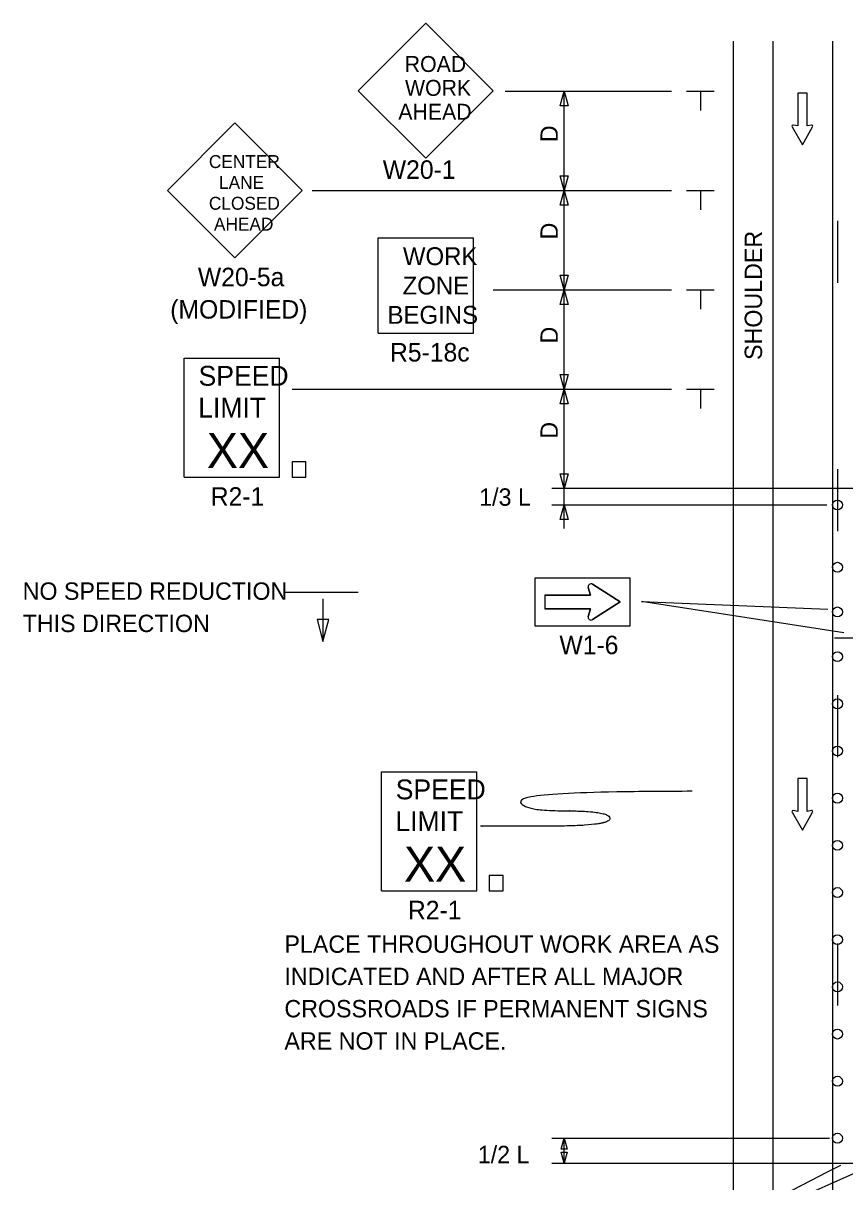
# Model space of a CAD drawing. Extents: x 16750 to 18306, y 5932 to 6925.
# Drawn here: x 16749.5 to 17080.6, y 6458.2 to 6924.9 of the extents above; entities that cross this region are included whole.
import ezdxf

# ---------------------------------------------------------------- set-up
doc = ezdxf.new("R2010")
doc.units = 0
for name, color, linetype in [('BORDER', 7, 'Continuous'), ('Level 3', 7, 'Continuous'), ('MT_SCRATCH_LEVEL_A', 7, 'Continuous'), ('MT_SCRATCH_LEVEL_E', 7, 'Continuous'), ('PAVT_EDGE_EX', 7, 'Continuous'), ('TRAFFIC_SIGNS_PR', 7, 'Continuous'), ('TYPICAL_EX', 7, 'Continuous'), ('TYPICAL_TEXT_DIMEN_EX', 7, 'Continuous'), ('TYPICAL_TEXT_DIMEN_PR', 7, 'Continuous')]:
    doc.layers.add(name, color=color, linetype=linetype)

msp = doc.modelspace()

# ---------------------------------------------------------------- linework, layer by layer
at = {"layer": 'BORDER'}
msp.add_line((17051.59, 6917.57), (17051.59, 6063.18), dxfattribs=at)
at = {"layer": 'Level 3'}
msp.add_line((17080.12, 6679.35), (16998.62, 6691.92), dxfattribs=at)
at = {"layer": 'MT_SCRATCH_LEVEL_A'}
for p, q in [((16911.72, 6924.87), (16884.53, 6897.68)), ((16938.9, 6897.68), (16911.72, 6924.87)), ((17075.59, 6917.57), (17075.59, 6063.18)), ((16884.53, 6897.68), (16911.72, 6870.49)), ((16911.72, 6870.49), (16938.9, 6897.68))]:
    msp.add_line(p, q, dxfattribs=at)
for points in [[(17077.59, 6845.22), (17077.59, 6820.22)], [(17077.59, 6745.22), (17077.59, 6720.22)], [(17077.59, 6654.22), (17077.59, 6629.22)], [(17077.59, 6554.22), (17077.59, 6529.22)]]:
    msp.add_lwpolyline(points, dxfattribs=at)
at = {"layer": 'MT_SCRATCH_LEVEL_E'}
for p, q in [((17065.33, 6896.74), (17061.59, 6896.74)), ((17061.59, 6896.74), (17061.59, 6883.48)), ((17065.33, 6896.74), (17061.59, 6896.74)), ((17061.59, 6896.74), (17061.59, 6883.48)), ((17065.33, 6883.48), (17065.33, 6896.74)), ((17065.33, 6883.48), (17065.33, 6896.74)), ((17061.59, 6883.48), (17059.81, 6883.79)), ((17061.59, 6883.48), (17059.81, 6883.79)), ((17067.11, 6883.79), (17065.33, 6883.48)), ((17067.11, 6883.79), (17065.33, 6883.48)), ((17059.33, 6883.11), (17063.48, 6875.87)), ((17059.33, 6883.11), (17063.48, 6875.87)), ((17063.48, 6875.87), (17067.59, 6883.11)), ((17063.48, 6875.87), (17067.59, 6883.11)), ((17065.33, 6620.66), (17061.59, 6620.66)), ((17061.59, 6620.66), (17061.59, 6607.4)), ((17065.33, 6620.66), (17061.59, 6620.66)), ((17061.59, 6620.66), (17061.59, 6607.4)), ((17065.33, 6607.4), (17065.33, 6620.66)), ((17065.33, 6607.4), (17065.33, 6620.66)), ((17059.33, 6607.03), (17063.48, 6599.79)), ((17059.33, 6607.03), (17063.48, 6599.79)), ((17061.59, 6607.4), (17059.81, 6607.72)), ((17061.59, 6607.4), (17059.81, 6607.72)), ((17063.48, 6599.79), (17067.59, 6607.03)), ((17063.48, 6599.79), (17067.59, 6607.03)), ((17067.11, 6607.72), (17065.33, 6607.4)), ((17067.11, 6607.72), (17065.33, 6607.4))]:
    msp.add_line(p, q, dxfattribs=at)
for centre, start, end in [((17059.74, 6883.33), 80.0362, 209.7731), ((17059.74, 6883.33), 80.0362, 209.7731), ((17067.18, 6883.33), 330.4248, 99.9638), ((17067.18, 6883.33), 330.4248, 99.9638), ((17059.74, 6607.26), 80.0362, 209.7731), ((17059.74, 6607.26), 80.0362, 209.7731), ((17067.18, 6607.26), 330.4248, 99.9638), ((17067.18, 6607.26), 330.4248, 99.9638)]:
    msp.add_arc(centre, 0.463, start, end, dxfattribs=at)
at = {"layer": 'PAVT_EDGE_EX'}
msp.add_line((17035.59, 6917.57), (17035.59, 6063.18), dxfattribs=at)
at = {"layer": 'TRAFFIC_SIGNS_PR'}
for p, q in [((16884.53, 6897.68), (16911.72, 6924.87)), ((16911.72, 6924.87), (16938.9, 6897.68)), ((16911.72, 6870.49), (16884.53, 6897.68)), ((16938.9, 6897.68), (16911.72, 6870.49)), ((16834.77, 6884.67), (16807.62, 6857.51)), ((16861.92, 6857.51), (16834.77, 6884.67)), ((16807.62, 6857.51), (16834.77, 6830.36)), ((16834.77, 6830.36), (16861.92, 6857.51)), ((16892.51, 6800.03), (16892.51, 6838.43)), ((16892.51, 6838.43), (16930.91, 6838.43)), ((16930.91, 6800.03), (16930.91, 6838.43)), ((16892.51, 6800.03), (16930.91, 6800.03)), ((16814.42, 6789.98), (16852.82, 6789.98)), ((16814.42, 6741.98), (16814.42, 6789.98)), ((16852.82, 6741.98), (16852.82, 6789.98)), ((16814.42, 6741.98), (16852.82, 6741.98)), ((16978.04, 6694.55), (16977.2, 6697.61)), ((16978.88, 6698.86), (16990.04, 6691.75)), ((16959.64, 6694.55), (16978.04, 6694.55)), ((16959.64, 6694.55), (16959.64, 6688.95)), ((16978.04, 6688.95), (16959.64, 6688.95)), ((16977.2, 6685.89), (16978.04, 6688.95)), ((16990.04, 6691.75), (16978.88, 6684.65)), ((16893.86, 6623.39), (16932.26, 6623.39)), ((16893.86, 6575.39), (16893.86, 6623.39)), ((16932.26, 6575.39), (16932.26, 6623.39)), ((16893.86, 6575.39), (16932.26, 6575.39))]:
    msp.add_line(p, q, dxfattribs=at)
for points in [[(16857.84, 6741.98), (16863.43, 6741.98), (16863.43, 6748.15), (16857.84, 6748.15)], [(16955.64, 6682.15), (16994.04, 6682.15), (16994.04, 6701.35), (16955.64, 6701.35)], [(16937.27, 6575.39), (16942.87, 6575.39), (16942.87, 6581.56), (16937.27, 6581.56)]]:
    msp.add_lwpolyline(points, close=True, dxfattribs=at)
for points in [[(16977.2, 6697.61), (16978.04, 6694.55), (16959.64, 6694.55), (16959.64, 6688.95), (16978.04, 6688.95), (16977.2, 6685.89)], [(16978.88, 6684.65), (16990.04, 6691.75), (16978.88, 6698.86)]]:
    msp.add_lwpolyline(points, dxfattribs=at)
for centre in [(17077.59, 6730.81), (17077.59, 6705.72), (17077.59, 6687.72), (17077.59, 6669.72), (17077.59, 6650.72), (17077.59, 6631.72), (17077.59, 6612.72), (17077.59, 6593.72), (17077.59, 6574.72), (17077.59, 6555.72), (17077.59, 6536.72), (17077.59, 6517.72), (17077.59, 6498.72), (17077.59, 6475.75)]:
    msp.add_circle(centre, 2, dxfattribs=at)
for centre, start, end in [((16978.28, 6697.91), 57.5304, 195.3269), ((16978.28, 6697.91), 57.5304, 195.3269), ((16978.28, 6685.6), 164.6731, 302.4696), ((16978.28, 6685.6), 164.6731, 302.4696)]:
    msp.add_arc(centre, 1.12, start, end, dxfattribs=at)
at = {"layer": 'TYPICAL_EX'}
for p, q in [((17016.74, 6897.47), (17027.99, 6897.47)), ((17022.37, 6897.47), (17022.37, 6889.69)), ((17016.74, 6857.47), (17027.99, 6857.47)), ((17022.37, 6857.47), (17022.37, 6849.69)), ((17016.74, 6817.47), (17027.99, 6817.47)), ((17022.37, 6817.47), (17022.37, 6809.69)), ((17016.74, 6777.47), (17027.99, 6777.47)), ((17022.37, 6777.47), (17022.37, 6769.69)), ((17087.66, 6677.17), (17076.41, 6677.17))]:
    msp.add_line(p, q, dxfattribs=at)
at = {"layer": 'TYPICAL_TEXT_DIMEN_PR'}
for p, q in [((16943.76, 6897.47), (17010.69, 6897.47)), ((16965.92, 6891.61), (16967.49, 6897.47)), ((16967.49, 6897.47), (16969.06, 6891.61)), ((16967.49, 6857.47), (16967.49, 6897.47)), ((16967.49, 6891.61), (16965.92, 6891.61)), ((16969.06, 6891.61), (16967.49, 6891.61)), ((16967.49, 6857.47), (16965.92, 6863.34)), ((16965.92, 6863.34), (16967.49, 6863.34)), ((16967.49, 6863.34), (16969.06, 6863.34)), ((16969.06, 6863.34), (16967.49, 6857.47)), ((16866.01, 6857.47), (17010.69, 6857.47)), ((16965.92, 6851.61), (16967.49, 6857.47)), ((16967.49, 6817.47), (16967.49, 6857.47)), ((16967.49, 6857.47), (16969.06, 6851.61)), ((16967.49, 6851.61), (16965.92, 6851.61)), ((16969.06, 6851.61), (16967.49, 6851.61)), ((16967.49, 6817.47), (16965.92, 6823.34)), ((16965.92, 6823.34), (16967.49, 6823.34)), ((16967.49, 6823.34), (16969.06, 6823.34)), ((16969.06, 6823.34), (16967.49, 6817.47)), ((16938.9, 6817.47), (17010.69, 6817.47)), ((16965.92, 6811.61), (16967.49, 6817.47)), ((16967.49, 6817.47), (16969.06, 6811.61)), ((16967.49, 6777.47), (16967.49, 6817.47)), ((16967.49, 6811.61), (16965.92, 6811.61)), ((16969.06, 6811.61), (16967.49, 6811.61)), ((16967.49, 6777.47), (16965.92, 6783.34)), ((16965.92, 6783.34), (16967.49, 6783.34)), ((16967.49, 6783.34), (16969.06, 6783.34)), ((16969.06, 6783.34), (16967.49, 6777.47)), ((16857.91, 6777.47), (17010.69, 6777.47)), ((16965.92, 6771.61), (16967.49, 6777.47)), ((16967.49, 6777.47), (16969.06, 6771.61)), ((16967.49, 6737.47), (16967.49, 6777.47)), ((16967.49, 6771.61), (16965.92, 6771.61)), ((16969.06, 6771.61), (16967.49, 6771.61)), ((16967.49, 6737.47), (16965.92, 6743.34)), ((16965.92, 6743.34), (16967.49, 6743.34)), ((16967.49, 6743.34), (16969.06, 6743.34)), ((16969.06, 6743.34), (16967.49, 6737.47)), ((17093.86, 6737.47), (16962.49, 6737.47)), ((16967.49, 6721.4), (16967.49, 6737.47)), ((16962.49, 6730.81), (17073.36, 6730.81)), ((16965.92, 6724.94), (16967.49, 6730.81)), ((16967.49, 6730.81), (16969.06, 6724.94)), ((16967.49, 6724.94), (16965.92, 6724.94)), ((16969.06, 6724.94), (16967.49, 6724.94)), ((16884.47, 6695.5), (16855.03, 6695.5)), ((16870.29, 6693), (16870.29, 6675.88)), ((16998.62, 6691.92), (17073.76, 6688.79)), ((16870.29, 6684.67), (16867.94, 6684.67)), ((16867.94, 6684.67), (16870.29, 6675.88)), ((16870.29, 6675.88), (16872.65, 6684.67)), ((16872.65, 6684.67), (16870.29, 6684.67)), ((16962.49, 6475.75), (17074.39, 6475.75)), ((16966.31, 6471.35), (16967.49, 6475.75)), ((16967.49, 6475.75), (16968.67, 6471.35)), ((16967.49, 6465.75), (16967.49, 6475.75)), ((16967.49, 6471.35), (16966.31, 6471.35)), ((16967.49, 6465.75), (16966.31, 6470.15)), ((16966.31, 6470.15), (16967.49, 6470.15)), ((16968.67, 6471.35), (16967.49, 6471.35)), ((16967.49, 6470.15), (16968.67, 6470.15)), ((16968.67, 6470.15), (16967.49, 6465.75)), ((16962.49, 6465.75), (17094.29, 6465.75)), ((17001.57, 6424.99), (17091.23, 6464.75)), ((17073.53, 6462.17), (17078.94, 6464.96)), ((17001.57, 6424.99), (17073.53, 6462.17))]:
    msp.add_line(p, q, dxfattribs=at)
msp.add_open_spline([(17019.08, 6615.49), (16950, 6615.49), (16950, 6607.61), (16985.96, 6607.61), (16985.96, 6601.45), (16937.66, 6601.45), (16933.72, 6601.45)], degree=2, dxfattribs=at)

# ---------------------------------------------------------------- texts
at = {"layer": 'TRAFFIC_SIGNS_PR'}
for s, height, p in [('ROAD', 6.408, (16903.25, 6905.22)), ('WORK', 6.408, (16903.36, 6895.61)), ('AHEAD', 6.408, (16900.66, 6886)), ('CENTER', 5.2, (16824.35, 6866.52)), ('W20-1', 7.449, (16894.4, 6862.17)), ('LANE', 5.2, (16828.42, 6858.12)), ('CLOSED', 5.2, (16824.35, 6849.72)), ('AHEAD', 5.2, (16826.38, 6841.32)), ('WORK', 7.217, (16902.51, 6827.4)), ('W20-5a', 7.44, (16819.91, 6818.92)), ('ZONE', 7.217, (16902.39, 6815.59)), ('(MODIFIED)', 7.44, (16808.77, 6805.88)), ('BEGINS', 7.217, (16896.32, 6803.78)), ('R5-18c', 7.44, (16897.32, 6788.59)), ('SPEED', 8, (16820.19, 6778.84)), ('LIMIT', 8, (16820.03, 6766.04)), ('XX', 14.031, (16823.54, 6745.73)), ('R2-1', 7.44, (16825.1, 6730.53)), ('W1-6', 7.44, (16965.58, 6670.71)), ('SPEED', 8, (16899.62, 6612.25)), ('LIMIT', 8, (16899.46, 6599.45)), ('XX', 14.031, (16902.97, 6579.15)), ('R2-1', 7.44, (16904.53, 6563.95)), ('PLACE THROUGHOUT WORK AREA AS', 7, (16854.78, 6550.43)), ('INDICATED AND AFTER ALL MAJOR', 7, (16854.78, 6537.43)), ('CROSSROADS IF PERMANENT SIGNS', 7, (16854.78, 6524.43)), ('ARE NOT IN PLACE.', 7, (16854.78, 6511.43))]:
    msp.add_text(s, height=height, dxfattribs=at).set_placement(p)
at = {"layer": 'TYPICAL_TEXT_DIMEN_EX'}
msp.add_text('SHOULDER', height=7, rotation=90, dxfattribs=at).set_placement((17047.22, 6789.22))
at = {"layer": 'TYPICAL_TEXT_DIMEN_PR'}
for p in [(16964.93, 6876.93), (16964.93, 6837.75), (16964.93, 6795.84), (16964.93, 6757.5)]:
    msp.add_text('D', height=7, rotation=90, dxfattribs=at).set_placement(p)
for s, p in [('1/3 L', (16933.25, 6730.5)), ('NO SPEED REDUCTION', (16749.31, 6692.62)), ('THIS DIRECTION', (16749.31, 6679.62)), ('1/2 L', (16932.69, 6465.7))]:
    msp.add_text(s, height=7, dxfattribs=at).set_placement(p)

doc.saveas('drawing.dxf')
